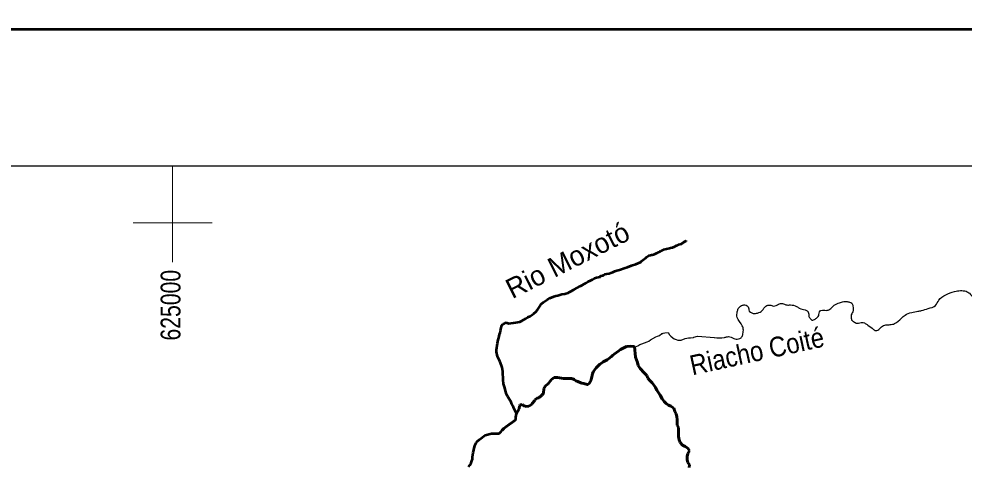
# Model space of a CAD drawing. Extents: x -1643653 to 4543381, y 1624270 to 13878484.
# Drawn here: x 621120 to 644975, y 9018855 to 9030146 of the extents above; entities that cross this region are included whole.
import ezdxf
from ezdxf.enums import TextEntityAlignment as Align

# ---------------------------------------------------------------- set-up
doc = ezdxf.new("R2010")
doc.units = 0
doc.header["$LTSCALE"] = 200
doc.linetypes.add('LONG_DASH_SHORT_DASH', pattern=[9.9, 6, -1.2, 1.5, -1.2])
for name, color, linetype, lineweight in [('2', 7, 'Continuous', 13), ('24', 7, 'Continuous', 25), ('3', 7, 'Continuous', 13), ('60', 7, 'Continuous', 13), ('7', 7, 'LONG_DASH_SHORT_DASH', 60)]:
    doc.layers.add(name, color=color, linetype=linetype, lineweight=lineweight)
doc.layers.add('47', color=7, linetype='Continuous')
doc.layers.add('49', color=7, linetype='Continuous')

msp = doc.modelspace()

# ---------------------------------------------------------------- linework, layer by layer
at = {"layer": '2'}
for p, q in [((625000, 9024000), (625000, 9026438.8)), ((624000, 9025000), (626000, 9025000))]:
    msp.add_line(p, q, dxfattribs=at)
at = {"layer": '24', "lineweight": 53}
for points in [[(633413.9, 9022478.1), (633421.2, 9022477.1), (633480.4, 9022458.5), (633606.6, 9022474.9), (633658.1, 9022477.9), (633711.2, 9022491.3), (633762.6, 9022500.8), (633814.1, 9022520.8), (633917, 9022578.5), (633968.6, 9022613.4), (634020, 9022642.8), (634070.1, 9022674), (634114.4, 9022705.1), (634164.6, 9022749.5), (634211.6, 9022799.5), (634275.4, 9022905.1), (634276.2, 9022912.6), (634313.5, 9022956), (634360.5, 9022996.6), (634407, 9023028.7), (634463.3, 9023060.8), (634516.2, 9023093.9), (634619.2, 9023138.5), (634669.3, 9023151.8), (634720.7, 9023158.6), (634772.3, 9023177.5), (634823.9, 9023193.7), (634887.8, 9023203.3), (634902.5, 9023207.1), (634926.9, 9023210), (634978.4, 9023232.8), (635028.4, 9023251.7), (635132.8, 9023316), (635288.5, 9023394.6), (635338.7, 9023423), (635440.3, 9023486.3), (635485.1, 9023511.9), (635543.2, 9023541.2), (635595.9, 9023564.9), (635650.6, 9023598), (635699.1, 9023616), (635790.3, 9023636.1), (635793.1, 9023638), (635800.1, 9023649.3), (635819, 9023660.6), (635853.4, 9023668.3), (635876.7, 9023676.8), (635906.5, 9023697.6), (635956.5, 9023710), (636013.3, 9023718.7), (636059.5, 9023732.9), (636105.8, 9023750.9), (636162.5, 9023775.6), (636212.6, 9023793.6), (636275.1, 9023811.7), (636425, 9023859.2), (636478, 9023881.9), (636577.8, 9023919.9), (636690.9, 9023956), (636806.1, 9024008.1), (636823.2, 9024013.8), (636845.9, 9024034.6), (636912.2, 9024085.6), (636934.8, 9024108.2), (636956.3, 9024126.2), (637018.2, 9024171.5), (637057.1, 9024184.8), (637082.8, 9024185.8), (637104.5, 9024187.8), (637134.2, 9024195.4), (637161.3, 9024208.7), (637216.1, 9024229.5), (637230.8, 9024237.1), (637250.3, 9024253.2), (637273.6, 9024257.9), (637295.2, 9024272.1), (637314.4, 9024282.5), (637334, 9024298.6), (637359.5, 9024308.1), (637385.3, 9024320.4), (637537.2, 9024359.4), (637566.8, 9024363.3), (637618.3, 9024376.6), (637671, 9024396.6), (637718.9, 9024421.2), (637745.8, 9024437.2), (637770.3, 9024449.6), (637846.7, 9024469.6), (637851.3, 9024475.2), (637892.7, 9024501.7), (637913.2, 9024518.7), (637958, 9024544.2), (637971.9, 9024555.7)], [(633676.3, 9020181.4), (633676.3, 9020181.4), (633638.7, 9020264), (633612.2, 9020317.5), (633591.7, 9020369.2), (633563.5, 9020419.9), (633539.8, 9020471.5), (633453.9, 9020622.6), (633428.7, 9020672.4), (633401.8, 9020755.1), (633381.4, 9020829.3), (633365.3, 9020880), (633352.2, 9020933.6), (633345.6, 9021033.3), (633345, 9021086.9), (633332.3, 9021186.5), (633331.6, 9021241.1), (633318.4, 9021341.7), (633300.6, 9021397.1), (633254.7, 9021503.2), (633213.2, 9021588.7)], [(632466.2, 9018835.3), (632501.5, 9018878.7), (632534.3, 9018936.2), (632553, 9018986.1), (632567.9, 9019034.1), (632569.1, 9019090.5), (632581.5, 9019191.2), (632619.5, 9019345.6), (632634.6, 9019396.4), (632664.3, 9019445.4), (632694.5, 9019486.9), (632744.2, 9019530.3), (632884.7, 9019635.2), (633050.2, 9019677.1), (633151.8, 9019677.4), (633222.6, 9019674.8), (633250.5, 9019683.4), (633294.8, 9019725.8), (633324, 9019767.3), (633357, 9019804.1), (633398.5, 9019840), (633496.1, 9019905.2), (633581.5, 9019968.5), (633647.8, 9020012.9), (633658.1, 9020043.1), (633663.7, 9020077.9), (633660.2, 9020090.1), (633676, 9020172.9), (633676.3, 9020181.4)]]:
    msp.add_lwpolyline(points, dxfattribs=at)
at = {"layer": '24'}
for points in [[(636656.2, 9021865), (636684.9, 9021860.4), (636702.2, 9021873.6), (636740.9, 9021895.4), (636792.1, 9021921.9), (636838.7, 9021941.8), (636972.2, 9021990.2), (637015.9, 9022012), (637062.3, 9022041.3), (637193.3, 9022116), (637241.1, 9022134), (637284.8, 9022155.8), (637346, 9022200.2), (637368.3, 9022205), (637375.3, 9022213.5), (637379.5, 9022215.4), (637419.9, 9022224), (637504.2, 9022227.1), (637543.1, 9022171.7), (637575.9, 9022133.2), (637622.8, 9022093), (637661.8, 9022064.9), (637705.5, 9022049), (637750.8, 9022037), (637835.6, 9022037.2), (637934, 9022078.9), (637976.1, 9022088.5), (638019.7, 9022095.2), (638067.9, 9022095.4), (638139.8, 9022101.2), (638145.1, 9022104.1), (638157.6, 9022114.5), (638245.3, 9022132.2), (638672.6, 9022102.2)], [(636652.9, 9021868), (636641.6, 9021870.8), (636559.2, 9021880.9), (636454.2, 9021872.1), (636402.3, 9021849.3), (636354.6, 9021825.7), (636305.7, 9021795.4), (636263.9, 9021766.1), (636146.2, 9021677.3), (636105.2, 9021649), (636073, 9021625.4), (636004.2, 9021562.1), (635963.7, 9021536.6), (635867.3, 9021484.6), (635822.2, 9021456.2), (635780.5, 9021426.9), (635747.3, 9021396.7), (635692.5, 9021336.3), (635636.6, 9021264.7), (635616.1, 9021229.8), (635597.2, 9021191.2), (635584.4, 9021142.2), (635566, 9021043.4), (635559.6, 9021026.5), (635512, 9020943.6), (635480.4, 9020919), (635466.2, 9020917.1), (635380.8, 9020937.5), (635326.8, 9020945.8), (635298.1, 9020960.7), (635224.4, 9020989.6), (635174.2, 9021011.1), (635133.8, 9021040.1), (635075.6, 9021068.1), (634924.4, 9021068.6), (634868.1, 9021065.6), (634816.6, 9021072), (634714.8, 9021096.1), (634640.3, 9021095.8), (634633, 9021094.9), (634564.5, 9021042.9), (634472.5, 9020927.9), (634430.9, 9020895.8), (634394.5, 9020859), (634385.7, 9020847.7), (634383.8, 9020843), (634383.1, 9020829.8), (634371.1, 9020810.9), (634361.3, 9020698.1), (634352.5, 9020683), (634342.1, 9020680.1), (634329, 9020647.2), (634305.8, 9020635.8), (634240.7, 9020580.1), (634199.2, 9020572.4), (634144.7, 9020528.1), (634139.6, 9020509.2), (634131.3, 9020504.5), (634076.6, 9020431.9), (634046.6, 9020405.5), (633987.2, 9020367.7), (633978.5, 9020365.7), (633894.3, 9020363.6), (633891.4, 9020364.5), (633885.4, 9020372), (633871.8, 9020372.9), (633850.3, 9020386), (633845.5, 9020394.5), (633828.1, 9020398.2), (633817.3, 9020409.4), (633770.7, 9020403.6), (633766, 9020385.7), (633755.6, 9020376.3), (633753.8, 9020373.5), (633746.2, 9020297.3), (633676.3, 9020181.4)]]:
    msp.add_lwpolyline(points, dxfattribs=at)
msp.add_spline([(638666.8, 9022105.1), (638926.3, 9022102.2), (638999.8, 9022122.2), (639130, 9022095.5), (639190.1, 9022065.4), (639313.6, 9022075.5), (639347, 9022095.5), (639387.1, 9022169), (639403.7, 9022285.9), (639377, 9022396.2), (639250.2, 9022610), (639250.2, 9022753.6), (639276.9, 9022830.4), (639360.3, 9022907.3), (639440.5, 9022924), (639537.3, 9022850.5), (639540.6, 9022797), (639654.1, 9022710.2), (639764.3, 9022720.2), (639877.8, 9022780.3), (639974.6, 9022897.2), (640074.8, 9022920.6), (640164.9, 9022893.9), (640295.1, 9022944), (640388.6, 9022957.4), (640502.1, 9022924), (640592.2, 9022924), (640749.2, 9022883.9), (640785.9, 9022860.5), (640815.9, 9022843.8), (640962.8, 9022797), (641029.6, 9022760.3), (641042.9, 9022740.2), (641059.6, 9022633.3), (641109.7, 9022563.2), (641136.4, 9022543.1), (641216.5, 9022566.5), (641253.3, 9022593.2), (641266.6, 9022610), (641293.3, 9022630), (641323.4, 9022750.3), (641363.4, 9022787), (641433.5, 9022793.7), (641493.6, 9022787), (641583.8, 9022813.7), (641697.3, 9022920.6), (641827.5, 9022977.4), (641937.7, 9023010.8), (642004.4, 9023010.8), (642084.6, 9022997.5), (642144.6, 9022967.4), (642168, 9022893.9), (642164.7, 9022750.3), (642121.3, 9022650), (642128, 9022589.9), (642134.6, 9022543.1), (642208.1, 9022493), (642248.1, 9022466.3), (642378.3, 9022483), (642481.8, 9022459.6), (642548.6, 9022416.2), (642685.5, 9022306), (642718.9, 9022282.6), (642795.7, 9022289.2), (642892.5, 9022369.4), (643002.6, 9022419.5), (643109.5, 9022426.2), (643223, 9022452.9), (643393.2, 9022586.6), (643486.7, 9022666.7), (643653.6, 9022733.6), (643810.5, 9022763.6), (643904, 9022783.7), (644067.6, 9022833.8), (644254.6, 9022910.6), (644338, 9023047.6), (644511.6, 9023177.9), (644735.3, 9023264.7), (644882.2, 9023284.8), (645025.8, 9023268.1), (645112.6, 9023218), (645202.7, 9023094.3), (645276.1, 9022927.3), (645349.6, 9022797), (645376.3, 9022760.3), (645506.5, 9022767), (645686.2, 9022762.3), (645814, 9022826.2), (646040.5, 9022896), (646290.2, 9022977.3), (646464.4, 9023111)], degree=3, dxfattribs=at)
at = {"layer": '24', "lineweight": 53}
msp.add_spline([(633213.2, 9021588.7), (633176.5, 9021739.5), (633198.3, 9021957.3), (633285, 9022315.7), (633329, 9022430.2), (633413.9, 9022478.1)], degree=3, dxfattribs=at)
at = {"layer": '3', "lineweight": 53}
msp.add_lwpolyline([(840307.3, 9029887.8), (840307.3, 8886387.8), (560211.7, 8886387.8), (560211.7, 9029887.8)], close=True, dxfattribs=at)
msp.add_lwpolyline([(840307.3, 9029887.8), (840307.3, 8886387.8), (560211.7, 8886387.8), (560211.7, 9029887.8)], close=True, dxfattribs=at)
at = {"layer": '3', "lineweight": 25}
msp.add_lwpolyline([(563033.9, 9026438.8), (793061.1, 9026438.8), (793495.6, 8889836.8), (563468.3, 8889836.8)], close=True, dxfattribs=at)
at = {"layer": '60', "lineweight": 25}
msp.add_spline([(814781, 9009175.5), (814787.2, 9009173.4), (814796.9, 9009173.4), (814799.4, 9009172.4), (814805.1, 9009174.5), (814805.6, 9009176.5), (814811.7, 9009179.5), (814811.7, 9009179.5), (814801.5, 9009181), (814790.7, 9009181.5), (814784.1, 9009183.1), (814777.4, 9009185.1), (814778.4, 9009175.5)], degree=3, dxfattribs=at)
at = {"layer": '7'}
for points in [[(636652.9, 9021868), (636641.6, 9021870.8), (636559.2, 9021880.9), (636454.2, 9021872.1), (636402.3, 9021849.3), (636354.6, 9021825.7), (636305.7, 9021795.4), (636263.9, 9021766.1), (636146.2, 9021677.3), (636105.2, 9021649), (636073, 9021625.4), (636004.2, 9021562.1), (635963.7, 9021536.6), (635867.3, 9021484.6), (635822.2, 9021456.2), (635780.5, 9021426.9), (635747.3, 9021396.7), (635692.5, 9021336.3), (635636.6, 9021264.7), (635616.1, 9021229.8), (635597.2, 9021191.2), (635584.4, 9021142.2), (635566, 9021043.4), (635559.6, 9021026.5), (635512, 9020943.6), (635480.4, 9020919), (635466.2, 9020917.1), (635380.8, 9020937.5), (635326.8, 9020945.8), (635298.1, 9020960.7), (635224.4, 9020989.6), (635174.2, 9021011.1), (635133.8, 9021040.1), (635075.6, 9021068.1), (634924.4, 9021068.6), (634868.1, 9021065.6), (634816.6, 9021072), (634714.8, 9021096.1), (634640.3, 9021095.8), (634633, 9021094.9), (634564.5, 9021042.9), (634472.5, 9020927.9), (634430.9, 9020895.8), (634394.5, 9020859), (634385.7, 9020847.7), (634383.8, 9020843), (634383.1, 9020829.8), (634371.1, 9020810.9), (634361.3, 9020698.1), (634352.5, 9020683), (634342.1, 9020680.1), (634329, 9020647.2), (634305.8, 9020635.8), (634240.7, 9020580.1), (634199.2, 9020572.4), (634144.7, 9020528.1), (634139.6, 9020509.2), (634131.3, 9020504.5), (634076.6, 9020431.9), (634046.6, 9020405.5), (633987.2, 9020367.7), (633978.5, 9020365.7), (633894.3, 9020363.6), (633891.4, 9020364.5), (633885.4, 9020372), (633871.8, 9020372.9), (633850.3, 9020386), (633845.5, 9020394.5), (633828.1, 9020398.2), (633817.3, 9020409.4), (633770.7, 9020403.6), (633766, 9020385.7), (633755.6, 9020376.3), (633753.8, 9020373.5), (633746.2, 9020297.3), (633676.3, 9020181.4)], [(638035.6, 9018816.7), (638045.4, 9018887), (638002.5, 9018942.1), (637984.6, 9019017.3), (637986.8, 9019100.2), (638006.7, 9019173), (638041.6, 9019238.5), (638006.2, 9019308.6), (637935.7, 9019353.5), (637870.2, 9019383.3), (637807.2, 9019450.8), (637784.3, 9019518.5), (637768.9, 9019603.8), (637768.4, 9019759.5), (637765.6, 9019827.2), (637732.7, 9019892.4), (637732.2, 9020033), (637726.9, 9020100.7), (637706.6, 9020170.9), (637671.2, 9020236), (637648.2, 9020316.3), (637577.7, 9020368.7), (637514.8, 9020396), (637454.3, 9020436), (637403.9, 9020488.5), (637355.9, 9020556), (637307.9, 9020643.7), (637216.9, 9020773.9), (637189.1, 9020836.5), (637151.2, 9020894.1), (637100.7, 9020954.1), (637042.7, 9021016.6), (636994.7, 9021076.7), (636964.3, 9021146.8), (636898.8, 9021209.3), (636797.8, 9021321.9), (636752.3, 9021397), (636734.5, 9021467.2), (636684.8, 9021608.7), (636652.9, 9021875.9)], [(633316.8, 9019757.1), (633324, 9019767.3), (633357, 9019804.1), (633398.5, 9019840), (633496.1, 9019905.2), (633581.5, 9019968.5), (633647.8, 9020012.9), (633658.1, 9020043.1)]]:
    msp.add_lwpolyline(points, dxfattribs=at)

# ---------------------------------------------------------------- texts
at = {"layer": '47', "width": 0.8}
msp.add_text('625000', height=500, rotation=90, dxfattribs=at).set_placement((625197.3, 9022917.4), align=Align.CENTER)
at = {"layer": '49'}
msp.add_text('Rio Moxotó', height=500, rotation=26.825, dxfattribs=at).set_placement((635080.7, 9023830.7), align=Align.CENTER)
at = {"layer": '49', "width": 0.9}
msp.add_text('Riacho Coité', height=500, rotation=12.335, dxfattribs=at).set_placement((639799.3, 9021513.7), align=Align.CENTER)

doc.saveas('drawing.dxf')
